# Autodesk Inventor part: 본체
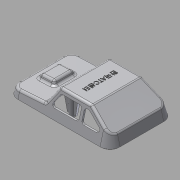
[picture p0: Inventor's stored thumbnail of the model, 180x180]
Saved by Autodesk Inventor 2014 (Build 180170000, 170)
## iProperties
Created: 2015-05
Part Number: 본체
Material: ABS 플라스틱
Document SubType Name: Modeling
Designer: Administrator
Density: 1.06 g/cm^3
Appearance: 매끄러움 - 흰색
Mass: 32.5997 g
Surface Area: 310.967 cm^2
Volume: 30.7544 cm^3
Author: Administrator
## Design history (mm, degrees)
sketch "스케치2"
  geometry: L1 (-49, -38)-(49, -38); L2 (61, -26)-(61, 26); L3 (49, 38)-(-49, 38); L4 (-61, 26)-(-61, -26); L5 (-61, -38)-(61, 38); L6 (61, -38)-(-61, 38); A1 r 12 centre (-49, 26) between (-49, 38) and (-61, 26); A2 r 12 centre (-49, -26) between (-61, -26) and (-49, -38); A3 r 12 centre (49, -26) between (49, -38) and (61, -26); A4 r 12 centre (49, 26) between (61, 26) and (49, 38); 1 further point
  constraints: 12 end point, 8 point on circle, 8 point on line, 8 tangent, 4 centre point, 3 equal radius, 2 midpoint, 2 parallel, 1 horizontal, 1 perpendicular
  dimensions: "d0" = 122 distance of L6.end L5.end; "d1" = 76 distance of L5.end L6.start; "d2" = 12 radius of A1
extrude "돌출1" new body sketch "스케치2" distance "d3" = 30; taper "d4" = -15 deg
sketch "스케치3"
  geometry: L1 (-31, 30)-(-61, 30); L2 (-61, 30)-(-61, 10); L3 (-61, 10)-(-31, 30); L4 (49, 30)-(-49, 30) reference; 3 further points
  constraints: 6 end point, 1 collinear, 1 horizontal, 1 midpoint, 1 perpendicular, 1 vertical alignment
  dimensions: "d5" = 30 distance of L1.start L1.end; "d6" = 20 distance of L1.end L2.end
extrude "돌출2" cut sketch "스케치3" stored distance "d7" = 30; taper "d8" = 0 deg
sketch "스케치4"
  geometry: L1 (61, 30)-(61, 8); L2 (19, 10.201)-(6.628, 30); L3 (6.628, 30)-(61, 30); L4 (49, 0)-(61, 0) reference; L5 (49, 30)-(-31, 30) reference; L6 (19, 10.201)-(61, 8); 2 further points
  constraints: 8 end point, 1 collinear, 1 midpoint, 1 perpendicular, 1 vertical, 1 vertical alignment
  dimensions: "d9" = 8 distance from line of L4 L1.end; "d13" = 42 horizontal distance of L2.start L1.start; "d15" = 3 deg angle of L4 L6; "d16" = 125 deg angle of L2 L6
extrude "돌출3" cut sketch "스케치4" stored distance "d17" = 30; taper "d18" = 0 deg
sketch "스케치5"
  geometry: L1 (-42.476, 9.267)-(-42.476, 61.267) reference; L2 (-31.476, 48.267)-(-11.476, 48.267); L3 (-11.476, 48.267)-(-11.476, 22.267); L4 (-11.476, 22.267)-(-31.476, 22.267); L5 (-31.476, 22.267)-(-31.476, 48.267); 2 further points
  constraints: 8 end point, 2 parallel, 1 horizontal, 1 horizontal alignment, 1 midpoint, 1 perpendicular
  dimensions: "d19" = 11 distance between parallel lines of L1 L5; "d20" = 26 distance of L2.end L3.end; "d21" = 20 distance of L2.start L2.end
extrude "돌출4" join sketch "스케치5" distance "d22" = 5; taper "d23" = -20 deg
fillet "모깎기1" dims "d24" = 3
fillet "모깎기2" dims "d25" = 3
fillet "모깎기3" dims "d26" = 3
feature "쉘1" dims "d27" = 2
sketch "스케치6"
  geometry: L1 (4.965, 30)-(-30.092, 30) reference; L2 (18.172, 11.526)-(7.51, 28.59) reference; L3 (-31.756, 29.496)-(-50.664, 16.891) reference; L4 (4.738, 23.59)-(10.362, 14.59); L5 (7.818, 10)-(-17.77, 10); L6 (-20.77, 13)-(-20.77, 22); L7 (-17.77, 25)-(2.194, 25); L8 (-30.242, 24.496)-(-43.742, 15.496); L9 (-28.578, 25)-(-26.986, 25); L10 (-23.986, 22)-(-23.986, 13); L11 (-26.986, 10)-(-42.078, 10); A1 r 3 centre (7.818, 13) between (7.818, 10) and (10.362, 14.59); A2 r 3 centre (2.194, 22) between (4.738, 23.59) and (2.194, 25); A3 r 3 centre (-17.77, 22) between (-17.77, 25) and (-20.77, 22); A4 r 3 centre (-17.77, 13) between (-20.77, 13) and (-17.77, 10); A5 r 3 centre (-26.986, 13) between (-26.986, 10) and (-23.986, 13); A6 r 3 centre (-26.986, 22) between (-23.986, 22) and (-26.986, 25); A7 r 3 centre (-28.578, 22) between (-28.578, 25) and (-30.242, 24.496); A8 r 3 centre (-42.078, 13) between (-43.742, 15.496) and (-42.078, 10); 7 further points
  constraints: 16 end point, 16 point on circle, 16 tangent, 12 point on line, 8 centre point, 7 equal radius, 4 parallel, 3 perpendicular, 1 collinear
  dimensions: "d28" = 5 distance between parallel lines of L2 L4; "d29" = 5 distance between parallel lines of L1 L7; "d30" = 34 distance of point (13.23, 10) point (-20.77, 10); "d31" = 15 distance of point (-20.77, 10) point (-20.77, 25); "d32" = 5 distance between parallel lines of L3 L8; "d33" = 5 distance between parallel lines of L1 L9; "d34" = 15 distance of point (-23.986, 25) point (-23.986, 10); "d35" = 28 distance of point (-23.986, 10) point (-51.986, 10); "d36" = 3 radius of A1
extrude "돌출5" cut sketch "스케치6" stored distance "d37" = 5; taper "d38" = 0 deg
sketch "스케치7"
  geometry: L1 (-49, 35.929)-(49, 35.929) reference; L2 (58.929, 26)-(58.929, -26) reference; L3 (49, -35.929)-(-49, -35.929) reference; L4 (-58.929, -26)-(-58.929, 26) reference; L5 (49, 36.929)-(-49, 36.929); L6 (-59.929, 26)-(-59.929, -26); L7 (-49, -36.929)-(49, -36.929); L8 (59.929, -26)-(59.929, 26); A1 r 9.929 centre (-49, 26) between (-49, 35.929) and (-58.929, 26) reference; A2 r 9.929 centre (49, 26) between (58.929, 26) and (49, 35.929) reference; A3 r 9.929 centre (49, -26) between (49, -35.929) and (58.929, -26) reference; A4 r 9.929 centre (-49, -26) between (-58.929, -26) and (-49, -35.929) reference; A5 r 10.929 centre (-49, 26) between (-49, 36.929) and (-59.929, 26); A6 r 10.929 centre (-49, -26) between (-59.929, -26) and (-49, -36.929); A7 r 10.929 centre (49, -26) between (49, -36.929) and (59.929, -26); A8 r 10.929 centre (49, 26) between (59.929, 26) and (49, 36.929); 1 further point
  constraints: 8 end point, 8 point on circle, 4 centre point, 7 other
  dimensions: "d39" = 1 distance between parallel lines of L1 L5
extrude "돌출6" join sketch "스케치7" distance "d40" = 1; taper "d41" = 0 deg
node "작업 평면1"
sketch "스케치8"
  geometry: L1 (-25, 0)-(-17, 0); L2 (-14, 0)-(-6, 0); L3 (6, 0)-(14, 0); L4 (17, 0)-(25, 0); A1 r 4 centre (-21, 0) between (-25, 0) and (-17, 0); A2 r 4 centre (-10, 0) between (-14, 0) and (-6, 0); A3 r 4 centre (10, 0) between (6, 0) and (14, 0); A4 r 4 centre (21, 0) between (17, 0) and (25, 0); 4 further points
  constraints: 8 end point, 8 point on circle, 4 centre point, 4 horizontal alignment, 10 other
  dimensions: "d43" = 8 diameter of A1; "d44" = 8 diameter of A2; "d45" = 8 diameter of A3; "d46" = 8 diameter of A4; "d47" = 10 distance of point (0, 0) A2.centre; "d48" = 20 distance of A3.centre A2.centre; "d49" = 11 distance of A1.centre A2.centre; "d50" = 11 distance of A4.centre A3.centre
extrude "돌출7" join sketch "스케치8" stored distance "d51" = 1; taper "d52" = 0 deg
chamfer "모따기1" distance "d53" = 1; stored, may be unused: second distance "d54" = 2, angle "d55" = 45 deg
sketch "스케치9"
  geometry: L1 (61, 26)-(61, -26) reference; 2 further points
  constraints: 1 horizontal alignment, 1 other
  dimensions: "d56" = 50 distance from line of L1 point (11, 0)
feature "엠보싱1" sketch "스케치9" dims "d0" = 122, "d1" = 76, "d2" = 12, "d57" = 0.5, "d58" = 0
sketch "스케치10"
  geometry: C1 r 3 at (40, 0); C2 r 3 at (0, 22); C3 r 3 at (0, -22); C4 r 3 at (-40, 0); 1 further point
  constraints: 4 centre point, 2 horizontal alignment, 2 vertical alignment
  dimensions: "d59" = 6 diameter of C1; "d60" = 6 diameter of C2; "d61" = 6 diameter of C3; "d62" = 6 diameter of C4; "d63" = 40 distance of C1.centre point (0, 0); "d64" = 40 distance of C4.centre point (0, 0); "d65" = 22 distance of C3.centre point (0, 0); "d66" = 44 distance of C3.centre C2.centre
extrude "돌출8" join sketch "스케치10" stored distance "d67" = 1; taper "d68" = 2 deg
node "작업 평면2"
sketch "스케치11"
  geometry: L1 (-45, -1)-(-35, -1); L2 (-35, -1)-(-35, 1); L3 (-35, 1)-(-45, 1); L4 (-45, 1)-(-45, -1); L5 (-45, -1)-(-35, 1); L6 (-35, -1)-(-45, 1); L7 (-5, 21)-(5, 21); L8 (5, 21)-(5, 23); L9 (5, 23)-(-5, 23); L10 (-5, 23)-(-5, 21); L11 (-5, 21)-(5, 23); L12 (5, 21)-(-5, 23); L13 (-5, -23)-(5, -23); L14 (5, -23)-(5, -21); L15 (5, -21)-(-5, -21); L16 (-5, -21)-(-5, -23); L17 (-5, -23)-(5, -21); L18 (5, -23)-(-5, -21); L19 (35, -1)-(45, -1); L20 (45, -1)-(45, 1); L21 (45, 1)-(35, 1); L22 (35, 1)-(35, -1); L23 (35, -1)-(45, 1); L24 (45, -1)-(35, 1); C1 r 3 at (-40, 0) reference; C2 r 3 at (0, 22) reference; C3 r 3 at (40, 0) reference; C4 r 3 at (0, -22) reference; 1 further point
  constraints: 48 end point, 8 midpoint, 8 parallel, 4 horizontal, 4 perpendicular
  dimensions: "d70" = 10 distance of L3.end L2.end; "d71" = 2 distance of L2.end L1.end; "d72" = 10 distance of L9.end L8.end; "d73" = 2 distance of L8.end L7.end; "d74" = 10 distance of L15.end L14.end; "d75" = 2 distance of L14.end L13.end; "d76" = 10 distance of L21.end L20.end; "d77" = 2 distance of L20.end L19.end
extrude "돌출9" join sketch "스케치11" stored distance "d78" = 1; taper "d79" = 2.5 deg
node "작업 평면4"
sketch "스케치22"
  geometry: L1 (-5, 2)-(-6.095, 27.079) reference; L2 (5, 2)-(6.135, 28) reference; L3 (3, 0)-(-3, 0) reference; L4 (0, 0)-(0, 28); L5 (5, 2)-(9.585, 28); L6 (-5, 2)-(-8.69, 22.927); L7 (-16.476, 10.466)-(-5.813, 27.53) reference; L8 (-8.69, 22.927)-(-6.095, 27.079); L9 (-6.095, 27.079)-(-5, 2); L10 (6.135, 28)-(5, 2); L11 (-4.965, 28)-(30.092, 28) reference; L12 (6.135, 28)-(9.585, 28)
  constraints: 14 end point, 3 collinear, 3 point on line, 1 perpendicular
  dimensions: "d123" = 10 deg angle of L6 L4; "d124" = 20 deg angle of L5 L6
extrude "돌출17" join sketch "스케치22" stored distance "d125" = 1; taper "d126" = 0 deg
sketch "스케치25"
  geometry: L1 (-45, 2)-(-45.69, 17.803) reference; L2 (-35, 2)-(-33.969, 25.617) reference; L3 (-49.555, 15.226)-(-30.646, 27.832) reference; L4 (-37, 0)-(-43, 0) reference; L5 (-40, 0)-(-40, 21.596); L6 (-45, 2)-(-47.566, 16.552); L7 (-35, 2)-(-30.418, 27.984); L8 (-47.566, 16.552)-(-45.69, 17.803); L9 (-33.969, 25.617)-(-30.418, 27.984); 1 further point
  constraints: 10 end point, 2 collinear, 2 point on line, 1 midpoint, 1 perpendicular
  dimensions: "d140" = 10 deg angle of L6 L5; "d141" = 20 deg angle of L7 L6
extrude "돌출19" join sketch "스케치25" stored distance "d142" = 1; taper "d143" = 0 deg
sketch "스케치26"
  geometry: L1 (43, 0)-(37, 0) reference; L2 (45, 2)-(45.429, 11.82) reference; L3 (35, 2)-(34.546, 12.39) reference; L4 (40, 0)-(40, 12.39); L5 (45, 2)-(46.742, 11.877); L6 (35, 2)-(33.168, 12.39); L7 (34.546, 12.39)-(33.168, 12.39); L8 (45.429, 11.82)-(46.742, 11.877); 1 further point
  constraints: 10 end point, 3 perpendicular, 1 midpoint, 1 point on line
  dimensions: "d144" = 10 deg angle of L4 L6; "d145" = 20 deg angle of L5 L6
extrude "돌출20" join sketch "스케치26" stored distance "d146" = 1; taper "d147" = 0 deg
sketch "스케치27"
  geometry: C1 r 3 at (0, 0) reference; C2 r 3 at (-40, 22) reference; C3 r 3 at (0, 44) reference; C4 r 3 at (40, 22) reference; 1 further point
hole "구멍3" sketch "스케치27" at (40, 22), (0, 44), (0, 0), (-40, 22) diameter "d148" = 3.242; stored, may be unused: countersink angle "d152" = 90 deg, drill point angle "d154" = 118 deg; dims "d149" = 9, "d150" = 4, "d151" = 2, "d153" = 11
node "솔리드1"
mirror "대칭3"
node "투영된 루프1"
node "투영된 루프2"
node "투영된 루프3"
node "투영된 루프10"
node "투영된 루프11"
node "투영된 루프12"
other parameters: "d42" = -63, "d69" = 2, "d112" = 100 deg, "d122" = -22
